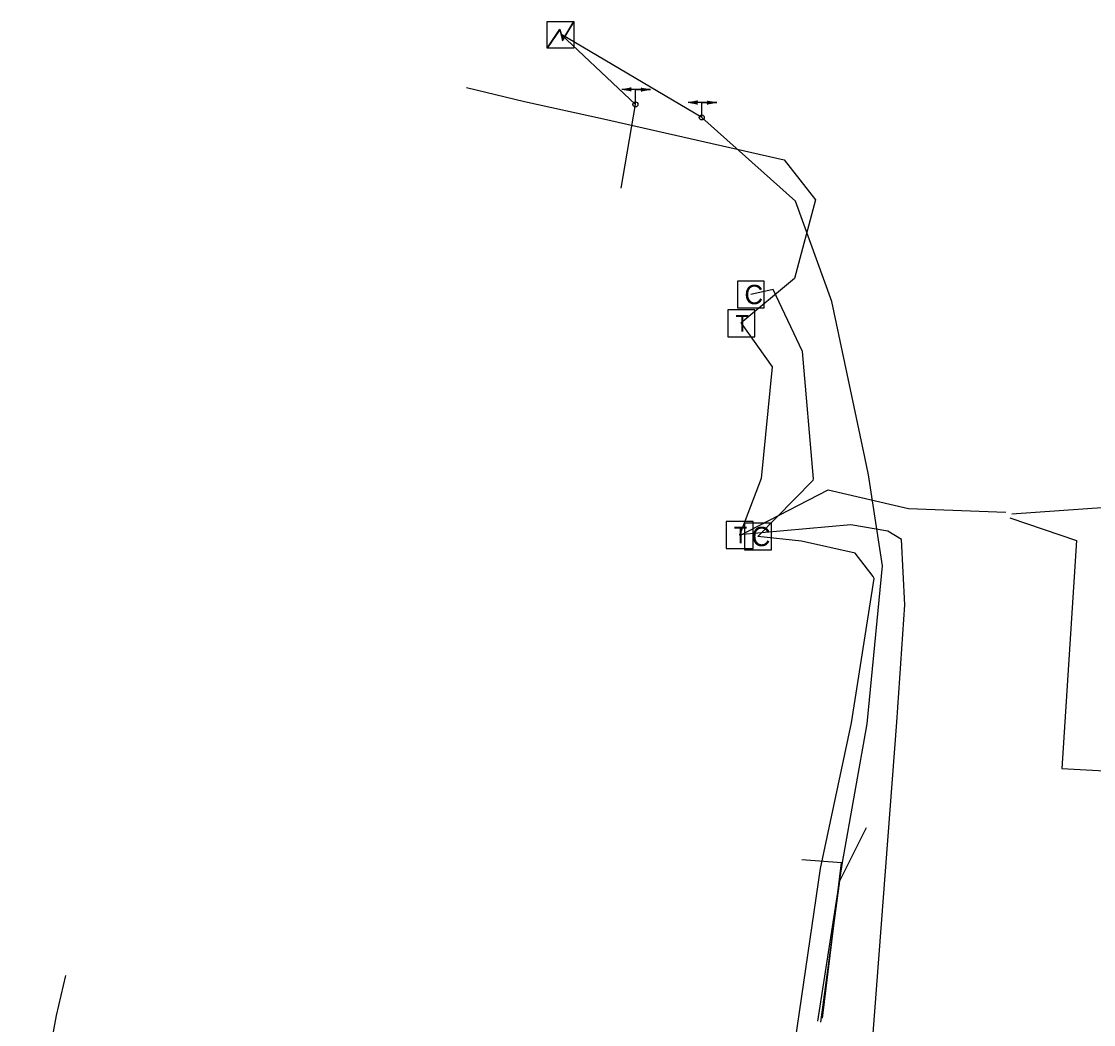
# Model space of a CAD drawing. Extents: x 2070721 to 2083039, y 729290 to 737883.
# Drawn here: x 2082142.2 to 2082364.3, y 736489 to 736696.6 of the extents above; entities that cross this region are included whole.
import ezdxf

# ---------------------------------------------------------------- set-up
doc = ezdxf.new("R2010")
doc.units = 0
for name, color, linetype in [('Cogo Default Point CELL', 7, 'Continuous'), ('Exist Utilities Power Pole Cogo Elevation', 7, 'Continuous'), ('Exist Utilities Power UG Cable Cogo Point CELL', 7, 'Continuous'), ('Exist Utilities Telephone UG Cable SUE LOS C Cogo Number', 7, 'Continuous'), ('Exist Utilities Telephone UG FO SUE LOS B Cogo Comment', 7, 'Continuous'), ('Exist Utilities TV UG Cable Cogo Point CELL', 7, 'Continuous'), ('Exist Utilities TV UG Cable SUE LOS C Cogo Comment', 7, 'Continuous'), ('Exist Utilities TV UG Cable SUE LOS C Cogo Elevation', 7, 'Continuous'), ('Exist Utilities Water UG Line SUE LOS B Cogo Elevation', 7, 'Continuous')]:
    doc.layers.add(name, color=color, linetype=linetype)

msp = doc.modelspace()

# ---------------------------------------------------------------- linework, layer by layer
at = {"layer": 'Cogo Default Point CELL'}
for p, q in [((2082293.28, 736640.1), (2082293.28, 736640.1)), ((2082294.78, 736590.01), (2082294.78, 736590.01))]:
    msp.add_line(p, q, dxfattribs=at)
for points in [[(2082290.51, 736637.32), (2082296.06, 736637.32), (2082296.06, 736642.87), (2082290.51, 736642.87), (2082290.51, 736637.32)], [(2082292, 736587.24), (2082297.55, 736587.24), (2082297.55, 736592.79), (2082292, 736592.79), (2082292, 736587.24)]]:
    msp.add_lwpolyline(points, dxfattribs=at)
at = {"layer": 'Exist Utilities Power Pole Cogo Elevation'}
for p in [(2082269.38, 736679.47), (2082283.12, 736676.76)]:
    msp.add_line(p, (2082253.92, 736694.03), dxfattribs=at)
at = {"layer": 'Exist Utilities Power UG Cable Cogo Point CELL'}
for p, q in [((2082272.52, 736682.55), (2082266.55, 736682.55)), ((2082269.38, 736679.47), (2082269.38, 736682.55)), ((2082269.38, 736682.55), (2082272.52, 736682.55)), ((2082269.38, 736679.47), (2082269.38, 736679.47)), ((2082286.25, 736679.84), (2082280.29, 736679.84)), ((2082283.12, 736676.76), (2082283.12, 736679.84)), ((2082283.12, 736679.84), (2082286.25, 736679.84)), ((2082283.12, 736676.76), (2082283.12, 736676.76))]:
    msp.add_line(p, q, dxfattribs=at)
for points in [[(2082266.55, 736682.55), (2082268.52, 736682.89), (2082268.11, 736682.55), (2082268.49, 736682.25)], [(2082272.52, 736682.55), (2082270.55, 736682.21), (2082270.97, 736682.55), (2082270.58, 736682.86)], [(2082280.29, 736679.84), (2082282.26, 736680.19), (2082281.84, 736679.84), (2082282.22, 736679.54)], [(2082286.25, 736679.84), (2082284.28, 736679.5), (2082284.7, 736679.84), (2082284.32, 736680.15)]]:
    msp.add_lwpolyline(points, close=True, dxfattribs=at)
for centre in [(2082269.38, 736679.47), (2082283.12, 736676.76)]:
    msp.add_circle(centre, 0.517, dxfattribs=at)
at = {"layer": 'Exist Utilities Telephone UG Cable SUE LOS C Cogo Number'}
msp.add_line((2082253.92, 736694.03), (2082253.92, 736694.03), dxfattribs=at)
msp.add_lwpolyline([(2082251.08, 736696.64), (2082256.63, 736696.64), (2082256.63, 736691.09), (2082251.08, 736691.09)], close=True, dxfattribs=at)
for points in [[(2082251.08, 736691.09), (2082253.72, 736695.03), (2082254.35, 736692.82), (2082256.63, 736696.64)], [(2082251.15, 736691.09), (2082253.72, 736694.82), (2082254.31, 736692.64), (2082256.63, 736696.49)]]:
    msp.add_lwpolyline(points, dxfattribs=at)
at = {"layer": 'Exist Utilities Telephone UG FO SUE LOS B Cogo Comment'}
for p, q in [((2082291.25, 736634.14), (2082291.25, 736634.14)), ((2082290.9, 736590.33), (2082290.9, 736590.33))]:
    msp.add_line(p, q, dxfattribs=at)
for points in [[(2082288.52, 736631.32), (2082294.11, 736631.32), (2082294.11, 736636.91), (2082288.52, 736636.91), (2082288.52, 736631.32)], [(2082288.18, 736587.5), (2082293.77, 736587.5), (2082293.77, 736593.09), (2082288.18, 736593.09), (2082288.18, 736587.5)]]:
    msp.add_lwpolyline(points, dxfattribs=at)
at = {"layer": 'Exist Utilities TV UG Cable Cogo Point CELL'}
for points in [[(2082234.39, 736682.96), (2082246.45, 736680.07), (2082262.79, 736676.47), (2082300.22, 736668.01), (2082306.68, 736659.69), (2082302.32, 736643.44), (2082291.24, 736634.14)], [(2082291.31, 736634.18), (2082297.74, 736625.14), (2082295.42, 736602), (2082290.98, 736590.39)], [(2082291.01, 736590.2), (2082309.31, 736599.68), (2082325.94, 736595.82), (2082346.11, 736595.07)], [(2082313.36, 736418.13), (2082323.5, 736551.56), (2082325.19, 736575.84), (2082324.51, 736589.38), (2082321.65, 736591.13), (2082314.03, 736592.42), (2082290.9, 736590.33)]]:
    msp.add_lwpolyline(points, dxfattribs=at)
at = {"layer": 'Exist Utilities TV UG Cable SUE LOS C Cogo Comment'}
msp.add_line((2082266.41, 736662.13), (2082269.38, 736679.47), dxfattribs=at)
for points in [[(2082316.9, 736606.43), (2082310.09, 736638.69), (2082302.53, 736659.4), (2082283.12, 736676.76)], [(2082307.19, 736489.63), (2082312.29, 736522.5), (2082317.39, 736551.2), (2082320.59, 736583.96), (2082317.63, 736602.74), (2082316.9, 736606.43)], [(2082307.78, 736489.42), (2082311.73, 736518.74), (2082317.25, 736529.76)], [(2082308.12, 736490.25), (2082312.09, 736522.45), (2082303.83, 736523.07)], [(2082142.24, 736451.57), (2082149.5, 736490.83), (2082151.41, 736499.09)]]:
    msp.add_lwpolyline(points, dxfattribs=at)
at = {"layer": 'Exist Utilities TV UG Cable SUE LOS C Cogo Elevation'}
for points in [[(2082294.76, 736589.99), (2082306.2, 736601.68), (2082306.27, 736601.95), (2082303.96, 736628.34), (2082297.91, 736641.15), (2082293.29, 736640.09)], [(2082346.94, 736593.86), (2082360.72, 736589.21), (2082357.72, 736541.97), (2082403.21, 736539.49), (2082428.03, 736538.87), (2082478.07, 736536.61), (2082484.59, 736536.15), (2082535.98, 736537.5), (2082560.91, 736538.33), (2082609.93, 736548.58), (2082615.28, 736549.68), (2082630.73, 736556.71), (2082655.26, 736576.14), (2082659.68, 736579.26), (2082669.26, 736584.45)], [(2082318.86, 736581.32), (2082318.64, 736581.7), (2082314.87, 736586.57), (2082303.81, 736589.07), (2082294.76, 736590)], [(2082291.62, 736436.42), (2082301.26, 736476.92), (2082307.72, 736521.26), (2082314.13, 736551.45), (2082318.86, 736581.32), (2082318.86, 736581.32)]]:
    msp.add_lwpolyline(points, dxfattribs=at)
at = {"layer": 'Exist Utilities Water UG Line SUE LOS B Cogo Elevation'}
msp.add_lwpolyline([(2082347.36, 736594.7), (2082407.12, 736598.92), (2082432.73, 736605.4), (2082485.1, 736604.34), (2082529.04, 736601.5), (2082560.83, 736601.5), (2082602.16, 736608.48), (2082660.87, 736631.23), (2082699.66, 736656.83), (2082708.35, 736665.58)], dxfattribs=at)

# ---------------------------------------------------------------- texts
at = {"layer": 'Cogo Default Point CELL'}
for p in [(2082291.97, 736638.1), (2082293.47, 736588.01)]:
    msp.add_text('C', height=4, dxfattribs=at).set_placement(p)
at = {"layer": 'Exist Utilities Telephone UG FO SUE LOS B Cogo Comment'}
for p in [(2082290.11, 736632.43), (2082289.77, 736588.61)]:
    msp.add_text('T', height=3.42, dxfattribs=at).set_placement(p)

doc.saveas('drawing.dxf')
